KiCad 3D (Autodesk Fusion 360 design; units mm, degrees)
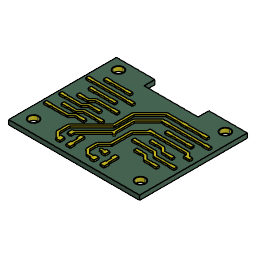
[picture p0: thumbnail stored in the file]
description: KiCad electronic assembly
part number: week8-assignment-3D 1
description: Part Number
part number: week8-assignment-3D_pad
part number: week8-assignment-3D_PCB
part number: week8-assignment-3D_copper
base_feature "Base Feature1"
base_feature "Base Feature1"
base_feature "Base Feature1"
combine "Combine1"
combine "Combine1"
extrude "Extrude1" add of existing geometry blind 0.005
extrude "Extrude1" add of existing geometry blind 0.005
extrude "Extrude2" add of existing geometry blind 0.5
extrude "Extrude2" add of existing geometry blind 0.5
extrude "Extrude3" add of existing geometry blind 0.5
extrude "Extrude3" add of existing geometry blind 0.5
extrude "Extrude4" add of existing geometry blind 0.5
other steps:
create_component "CreateComponent1"
create_component "CreateComponent2"
create_component "CreateComponent3"
remove_body "RemoveBody1"
remove_body "RemoveBody2"
remove_body "RemoveBody3"
remove_body "RemoveBody4"
remove_body "RemoveBody5"
remove_body "RemoveBody6"
remove_body "RemoveBody7"
remove_body "RemoveBody8"
remove_body "RemoveBody9"
remove_body "RemoveBody10"
remove_body "RemoveBody11"
remove_body "RemoveBody12"
remove_body "RemoveBody13"
remove_body "RemoveBody14"
remove_body "RemoveBody15"
remove_body "RemoveBody16"
remove_body "RemoveBody17"
remove_body "RemoveBody18"
remove_body "RemoveBody1"
remove_body "RemoveBody2"
remove_body "RemoveBody3"
remove_body "RemoveBody4"
remove_body "RemoveBody5"
remove_body "RemoveBody6"
remove_body "RemoveBody7"
remove_body "RemoveBody8"
remove_body "RemoveBody9"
